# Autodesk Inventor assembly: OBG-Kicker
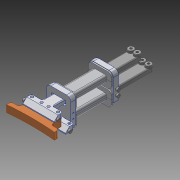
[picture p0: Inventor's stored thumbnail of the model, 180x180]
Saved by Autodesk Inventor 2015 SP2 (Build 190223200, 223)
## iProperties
Created: 2015-08
Part Number: OBG-Kicker
Document SubType Name: Assembly
Designer: rYan
Author: rYan
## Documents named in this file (6)
- D:\TIGERs GIT\Hardware\mechanik\2016\Inventor\Kicker\OBG-Kicker.iam
- D:\TIGERs GIT\Hardware\mechanik\2016\Inventor\Kicker\UBG-Spulen.iam
- D:\TIGERs GIT\Hardware\mechanik\2016\Inventor\Kicker\Straight\MG-Straight Kicker.iam
- D:\TIGERs GIT\Hardware\mechanik\2016\Inventor\Kicker\Chip\MG-Chip Kicker.iam
- D:\TIGERs GIT\Hardware\mechanik\2016\Inventor\Inhaltscenter\de-DE\ISO 4762(1)\ISO 4762 - M2 x 5DIN EN ISO.ipt
- D:\TIGERs GIT\Hardware\mechanik\2016\Inventor\Kaufteile\Gelpad 10x4.ipt
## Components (9 placed, 5 different names)
1. UBG-Spulen:1 [sub-assembly] — Fluchtend:9, Fluchtend:8, Passend:4, Passend:5, Fluchtend:4, Fluchtend:5, Fluchtend:6, Fluchtend:7, Passend:6, Passend:7, Einfügen:1, Einfügen:2, Einfügen:3, Einfügen:4
2. MG-Straight Kicker:1 [sub-assembly] — Fluchtend:9, Passend:7
3. MG-Chip Kicker:1 [sub-assembly] — Fluchtend:8, Passend:6
4. DIN EN ISO 4762 M2 x 5:1 — Einfügen:1
5. DIN EN ISO 4762 M2 x 5:2 — Einfügen:2
6. DIN EN ISO 4762 M2 x 5:3 — Einfügen:4
7. DIN EN ISO 4762 M2 x 5:4 — Einfügen:3
8. Gelpad 10x4:1 — Passend:5, Fluchtend:4, Fluchtend:5
9. Gelpad 10x4:2 — Passend:4, Fluchtend:6, Fluchtend:7
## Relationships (14: Flush 6, Mate 4, Insert 4)
- Fluchtend:9 [Flush]: UBG-Spulen:1 ↔ MG-Straight Kicker:1
- Fluchtend:8 [Flush]: UBG-Spulen:1 ↔ MG-Chip Kicker:1
- Passend:4 [Mate]: UBG-Spulen:1 ↔ Gelpad 10x4:2
- Passend:5 [Mate]: UBG-Spulen:1 ↔ Gelpad 10x4:1
- Fluchtend:4 [Flush]: UBG-Spulen:1 ↔ Gelpad 10x4:1
- Fluchtend:5 [Flush]: UBG-Spulen:1 ↔ Gelpad 10x4:1
- Fluchtend:6 [Flush]: UBG-Spulen:1 ↔ Gelpad 10x4:2
- Fluchtend:7 [Flush]: UBG-Spulen:1 ↔ Gelpad 10x4:2
- Passend:6 [Mate]: UBG-Spulen:1 ↔ MG-Chip Kicker:1
- Passend:7 [Mate]: UBG-Spulen:1 ↔ MG-Straight Kicker:1
- Einfügen:1 [Insert]: UBG-Spulen:1 ↔ DIN EN ISO 4762 M2 x 5:1
- Einfügen:2 [Insert]: UBG-Spulen:1 ↔ DIN EN ISO 4762 M2 x 5:2
- Einfügen:3 [Insert]: UBG-Spulen:1 ↔ DIN EN ISO 4762 M2 x 5:4
- Einfügen:4 [Insert]: UBG-Spulen:1 ↔ DIN EN ISO 4762 M2 x 5:3
